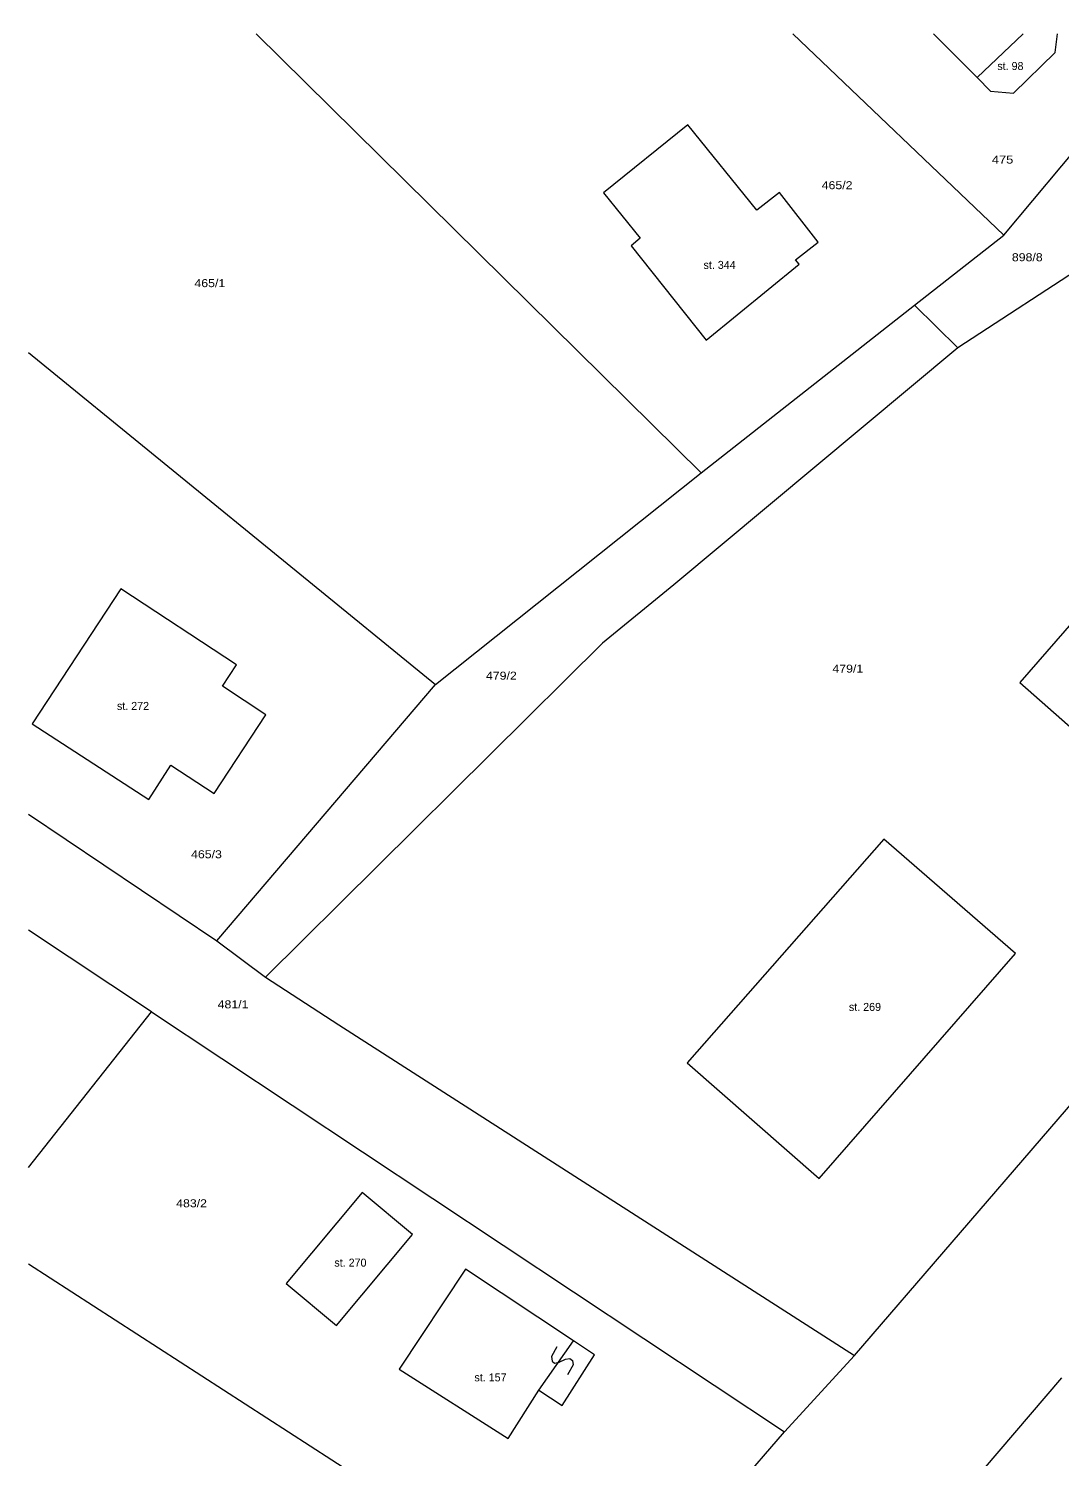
# Model space of a CAD drawing. Extents: x -694702 to -694000, y -1089746 to -1089192.
# Drawn here: x -694701.8 to -694637.4, y -1089487.5 to -1089398.3 of the extents above; entities that cross this region are included whole.
import ezdxf

# ---------------------------------------------------------------- set-up
doc = ezdxf.new("R2010")
doc.units = 0
doc.header["$LTSCALE"] = 0.2
doc.layers.add('50', color=7, linetype='Continuous', lineweight=13)
doc.layers.add('52', color=7, linetype='Continuous', lineweight=13)

msp = doc.modelspace()

# ---------------------------------------------------------------- linework, layer by layer
at = {"layer": '50'}
for p, q in [((-694640.89, -1089411.2), (-694630.11, -1089398.29)), ((-694659.79, -1089426.05), (-694687.58, -1089398.62)), ((-694640.89, -1089411.2), (-694654.06, -1089398.62)), ((-694642.54, -1089401.34), (-694639.68, -1089398.62)), ((-694646.47, -1089415.58), (-694640.89, -1089411.2)), ((-694633.81, -1089411.74), (-694643.75, -1089418.24)), ((-694659.79, -1089426.05), (-694646.47, -1089415.58)), ((-694643.75, -1089418.24), (-694646.47, -1089415.58)), ((-694701.8, -1089418.54), (-694676.38, -1089439.28)), ((-694676.38, -1089439.28), (-694659.79, -1089426.05)), ((-694694.13, -1089459.74), (-694701.8, -1089454.63)), ((-694690.05, -1089455.31), (-694687.01, -1089457.58)), ((-694701.8, -1089469.47), (-694694.13, -1089459.74)), ((-694694.13, -1089459.74), (-694654.58, -1089485.98)), ((-694701.8, -1089475.49), (-694665.71, -1089498.81)), ((-694669.93, -1089483.39), (-694667.76, -1089480.3)), ((-694654.58, -1089485.98), (-694650.22, -1089481.22)), ((-694637.28, -1089482.61), (-694650.77, -1089498.36)), ((-694665.71, -1089498.81), (-694654.58, -1089485.98))]:
    msp.add_line(p, q, dxfattribs=at)
for points in [[(-694645.27, -1089398.62), (-694642.54, -1089401.34), (-694641.71, -1089402.21), (-694640.28, -1089402.33), (-694637.67, -1089399.78), (-694637.54, -1089398.62)], [(-694643.75, -1089418.24), (-694661.49, -1089433.06), (-694665.96, -1089436.69), (-694687.01, -1089457.58)], [(-694650.22, -1089481.22), (-694631.91, -1089459.97), (-694609.14, -1089433.55)], [(-694701.8, -1089447.39), (-694690.05, -1089455.31), (-694676.38, -1089439.28)], [(-694687.01, -1089457.58), (-694682.43, -1089460.55), (-694650.22, -1089481.22)]]:
    msp.add_lwpolyline(points, dxfattribs=at)
for points in [[(-694656.31, -1089409.64), (-694660.62, -1089404.3), (-694665.88, -1089408.55), (-694663.59, -1089411.39), (-694664.17, -1089411.86), (-694659.47, -1089417.77), (-694653.66, -1089413.01), (-694653.89, -1089412.75), (-694652.47, -1089411.63), (-694654.89, -1089408.53)], [(-694631.65, -1089446.4), (-694619.57, -1089432.5), (-694627.78, -1089425.26), (-694639.88, -1089439.15)], [(-694701.58, -1089441.74), (-694694.29, -1089446.47), (-694692.92, -1089444.32), (-694690.21, -1089446.1), (-694686.97, -1089441.17), (-694689.69, -1089439.38), (-694688.81, -1089438.05), (-694696.04, -1089433.3)], [(-694660.67, -1089462.93), (-694652.42, -1089470.16), (-694640.15, -1089456.09), (-694648.37, -1089448.94)], [(-694677.82, -1089473.66), (-694680.97, -1089471.03), (-694685.71, -1089476.72), (-694682.56, -1089479.34)], [(-694667.76, -1089480.3), (-694674.5, -1089475.82), (-694678.65, -1089482.07), (-694671.85, -1089486.4), (-694669.93, -1089483.39), (-694668.46, -1089484.33), (-694666.45, -1089481.17)]]:
    msp.add_lwpolyline(points, close=True, dxfattribs=at)
at = {"layer": '52'}
msp.add_lwpolyline([(-694668.797, -1089480.662), (-694669.136, -1089481.274), (-694669.102, -1089481.559), (-694668.944, -1089481.684), (-694668.663, -1089481.637), (-694668.263, -1089481.44), (-694667.987, -1089481.401), (-694667.823, -1089481.518), (-694667.781, -1089481.807), (-694668.129, -1089482.415)], dxfattribs=at)

# ---------------------------------------------------------------- texts
for s, p in [('st. 98', (-694641.29, -1089400.88)), ('st. 344', (-694659.64, -1089413.31)), ('st. 272', (-694696.28, -1089440.87)), ('st. 269', (-694650.56, -1089459.68)), ('st. 270', (-694682.7, -1089475.66)), ('st. 157', (-694673.95, -1089482.83))]:
    msp.add_text(s, height=0.5, dxfattribs=at).set_placement(p)
for s, width, p in [('475', 1.2, (-694641.63, -1089406.73)), ('465/2', 1.15, (-694652.26, -1089408.33)), ('898/8', 1.15, (-694640.38, -1089412.83)), ('465/1', 1.15, (-694691.44, -1089414.45)), ('479/2', 1.15, (-694673.23, -1089438.98)), ('479/1', 1.15, (-694651.59, -1089438.54)), ('465/3', 1.15, (-694691.65, -1089450.14)), ('481/1', 1.15, (-694689.99, -1089459.52)), ('483/2', 1.15, (-694692.58, -1089471.95))]:
    msp.add_text(s, height=0.5, dxfattribs=dict(at, width=width)).set_placement(p)

doc.saveas('drawing.dxf')
